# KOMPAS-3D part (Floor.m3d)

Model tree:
1. Plane XY
2. Plane ZX
3. Plane ZY
4. X Axis
5. Y Axis
6. Z Axis
7. Origin
8. Sketch:1
9. Extrude:1
     Wall Thickness 1 = 1; Wall Thickness 2 = 1; Distance 1 = 10; Distance 2 = 10

Referenced files in D:\Documents and Settings\kashirsky\Рабочий стол\Cottage\: Cottage.a3d
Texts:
  Steel DIN 17102
  Three Point Plane
  Plane at Angle
  Line and Point Plane
  Axis through Two Vertices
  Axis of Feature
  Axis of Conical Surface
  Axis through Edge
  Trim by Surface
  Trim by Sketch
  Feature with No History
  Intersection Axis of Two Planes
  Two Line Plane
  Line and Face Plane
  Bend by line
  Hole in sheet body
  Cut in sheet body
  Point in CM
  Linear Dimension from Line to Point
  Surface Finish Symbol
  Geometric Tolerance Symbol
  Leader #1
  Leader #2
  Leader #3
  Shape Deviations and Datum
  Node point number
  Mark of coordination axis
  Node point designation
  Mark/Reference designation with leader
  Mark/reference designation on line
  Mark/Reference designation without leader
